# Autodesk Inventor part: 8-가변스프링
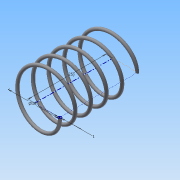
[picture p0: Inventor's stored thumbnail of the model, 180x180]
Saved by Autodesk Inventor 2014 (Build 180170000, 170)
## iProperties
Created: 2015-06
Part Number: 8-가변스프링
Material: 강철, 연강
Document SubType Name: Modeling
Designer: MYHOME
Density: 7.86 g/cm^3
Appearance: 강철
Mass: 1.53479 g
Surface Area: 7.89194 cm^2
Volume: 0.195266 cm^3
Author: MYHOME
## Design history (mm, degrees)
sketch "스케치1"
  geometry: L1 (0, 21.5)-(8, 21.5); L2 (8, 21.5)-(8, 0); L3 (8, 0)-(0, 0); L4 (0, 0)-(0, 21.5); C1 r 0.5 at (8, 0); 1 further point
  constraints: 8 end point, 3 coincident, 2 parallel, 1 centre point, 1 horizontal, 1 perpendicular
  dimensions: "d0" = 1 diameter of C1; "d1" = 16 diameter of L2 L4; "d2" = 21.5 distance of L3.end L1.start (derived)
feature "코일1" sketch "스케치1" pitch "d3" = 10; turns "d5" = 5; dims "d4" = 21.5 (= d2), "d6" = 0, angle "d7" = 90 deg, angle "d8" = 90 deg, "d9" = 0, "d10" = 0
sketch "스케치2"
  geometry: L1 (-8.5, 0)-(-7.5, 0) reference; 1 further point
  constraints: 1 horizontal alignment
extrude "돌출1" cut sketch "스케치2" stored distance "d11" = 10; taper "d12" = 0 deg
node "작업 평면1"
sketch "스케치3"
  geometry: L1 (-7.5, 0)-(-8.5, 0) reference; 1 further point
  constraints: 1 horizontal alignment
extrude "돌출2" cut sketch "스케치3" stored distance "d14" = 10; taper "d15" = 0 deg
node "솔리드1"
node "절단 모서리 투영1"
node "절단 모서리 투영2"
other parameters: "d13" = 21.5 (= d2)
